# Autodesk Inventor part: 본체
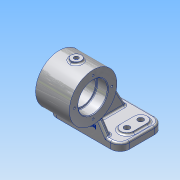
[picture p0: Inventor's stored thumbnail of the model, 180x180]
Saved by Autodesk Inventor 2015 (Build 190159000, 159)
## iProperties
Created: 2023-08
Part Number: 본체
Material: 알루미늄 6061
Document SubType Name: Modeling
Designer: 학생용
Density: 2.7 g/cm^3
Appearance: 알루미늄 - 평지
Mass: 777.808 g
Surface Area: 536.466 cm^2
Volume: 288.077 cm^3
Author: 학생용
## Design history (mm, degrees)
sketch "스케치1"
  geometry: L1 (-58, 12)-(58, 12); L2 (58, 12)-(58, 0); L3 (58, 0)-(-58, 0); L4 (-58, 0)-(-58, 12); 2 further points
  constraints: 8 end point, 2 parallel, 1 coincident, 1 horizontal, 1 midpoint, 1 perpendicular
  dimensions: "d0" = 116 distance of L2.end L3.end; "d1" = 12 distance of L1.end L2.end
extrude "돌출1" new body sketch "스케치1" stored distance "d2" = 70; taper "d3" = 0 deg
fillet "모깎기1" dims "d4" = 15
sketch "스케치2"
  geometry: L1 (84, 28)-(84, 50); L2 (94, 28)-(94, 50); L3 (74, 50)-(74, 28); L4 (43, 35)-(43, 87.935); L5 (2, 28)-(2, 50); L6 (-8, 28)-(-8, 50); L7 (12, 50)-(12, 28); L8 (0, 70)-(86, 70) reference; L9 (101, 15)-(101, 55) reference; A1 r 10 centre (84, 28) between (74, 28) and (94, 28); A2 r 10 centre (84, 50) between (94, 50) and (74, 50); A3 r 10 centre (2, 28) between (-8, 28) and (12, 28); A4 r 10 centre (2, 50) between (12, 50) and (-8, 50); 2 further points
  constraints: 18 end point, 8 point on circle, 6 symmetric about line, 4 centre point, 4 tangent, 2 vertical, 1 midpoint, 1 parallel, 2 other
  dimensions: "d6" = 20 distance between parallel lines of L3 L2; "d26" = 10 distance edge to line of A2 L8; "d28" = 22 distance of L1.start L1.end; "d73" = 82 distance of L1.end L5.end
extrude "돌출2" join sketch "스케치2" distance "d8" = 3; taper "d9" = 0 deg
sketch "스케치3"
  geometry: L1 (94, 28)-(94, 50) reference; L2 (74, 50)-(74, 28) reference; L3 (-8, 50)-(-8, 28) reference; L4 (12, 28)-(12, 50) reference; C1 r 4.5 at (84, 50); C2 r 4.5 at (84, 28); C3 r 4.5 at (2, 50); C4 r 4.5 at (2, 28); A1 r 10 centre (84, 50) between (94, 50) and (74, 50) reference; A2 r 10 centre (84, 28) between (74, 28) and (94, 28) reference; A3 r 10 centre (2, 28) between (-8, 28) and (12, 28) reference; A4 r 10 centre (2, 50) between (12, 50) and (-8, 50) reference; 1 further point
  constraints: 4 centre point, 4 coincident
  dimensions: "d10" = 9 diameter of C1; "d11" = 9 diameter of C2; "d12" = 9 diameter of C3; "d13" = 9 diameter of C4
extrude "돌출3" cut sketch "스케치3" stored distance "d14" = 3; taper "d15" = 0 deg
sketch "스케치4"
  geometry: L1 (12, 7)-(15, 7) reference; C1 r 38 at (70, 47); 1 further point
  constraints: 1 centre point
  dimensions: "d16" = 70 horizontal distance of point (0, 0) C1.centre; "d17" = 40 distance from line of C1.centre L1; "d18" = 76 diameter of C1
extrude "돌출4" join sketch "스케치4" stored distance "d19" = 54; taper "d20" = 0 deg
sketch "스케치5"
  geometry: L1 (-19.159, 37.933)-(-36, 12); L2 (-51, 12)-(-31, 12) reference; L3 (-58, 12)-(-58, 0) reference; L4 (0, 0)-(0, 51.675); L5 (19.159, 37.933)-(36, 12); L6 (-36, 12)-(36, 12); L7 (31, 12)-(51, 12) reference; L8 (-19.159, 37.933)-(19.159, 37.933)
  constraints: 10 end point, 2 symmetric about line, 1 collinear, 1 horizontal, 1 point on line, 1 vertical
  dimensions: "d21" = 33 deg angle of L3 L1; "d22" = 22 distance of L3.start L1.end; "d23" = 38.31786 distance of L1.start L5.start
extrude "돌출5" join sketch "스케치5" distance "d24" = 8; taper "d25" = 0 deg
sketch "스케치6"
  geometry: L1 (12, -27)-(87.882, 13.471); L2 (12, -35)-(0, -35) reference; L3 (12, -20)-(12, -35) reference; 2 further points
  constraints: 2 end point, 1 point on line, 3 other
  dimensions: "d77" = 8 distance from line of L2 L1.start
feature "리브1" sketch "스케치6" dims "d29" = 1, "d30" = 12, "d31" = 0, "d32" = 0, "d33" = 1, "d34" = 1
node "작업 평면2"
  node "작업 평면1"
sketch "스케치7"
  geometry: L1 (27, -38)-(27, 38) reference; L2 (27, 0)-(-27, 0); L3 (27, 0)-(27, 23.5); L4 (27, 23.5)-(10, 23.5); L5 (10, 23.5)-(10, 20.5); L6 (10, 20.5)-(-10, 20.5); L7 (-27, 38)-(-27, -38) reference; L8 (-27, 0)-(-27, 23.5); L9 (-27, 23.5)-(-10, 23.5); L10 (-10, 23.5)-(-10, 20.5); 1 further point
  constraints: 16 end point, 3 horizontal, 3 perpendicular, 2 point on line, 1 midpoint
  dimensions: "d36" = 47 diameter of L4 L2; "d37" = 41 diameter of L6 L2; "d38" = 17 distance of L3.end L4.end; "d40" = 17 distance of L8.end L9.end; "d41" = 47 diameter of L9 L2
revolve "회전1" sketch "스케치7" stored, may be unused: angle "d42" = 90 deg
sketch "스케치8" dims "d43" = 60
  geometry: C1 r 20.5 at (0, 0) reference; 6 further points
  constraints: 2 vertical alignment, 1 coincident, 7 other
  dimensions: "d46" = 360 deg dimension on C1.centre point (0, 30) (derived)
hole "구멍1" sketch "스케치8" at (0, 30), (-30, 0), (0, -30), (30, 0) diameter "d48" = 3.242; stored, may be unused: countersink angle "d52" = 90 deg, drill point angle "d54" = 120 deg; dims "d49" = 8, "d50" = 4, "d51" = 2, "d53" = 10
node "작업 평면3"
sketch "스케치9"
  geometry: L1 (27, 1.621)-(27, -1.621) reference; L2 (27, 0)-(-27, 0); L3 (-27, -1.621)-(-27, 1.621) reference; C1 r 8 at (0, 0); 2 further points
  constraints: 3 midpoint, 2 end point, 1 centre point, 1 coincident, 1 vertical alignment
  dimensions: "d55" = 16 diameter of C1
extrude "돌출6" join sketch "스케치9" distance "d56" = 3; taper "d58" = 0 deg; dims "d57" = 4, "d59" = 0
sketch "스케치10"
  geometry: C1 r 8 at (0, 0) reference; 2 further points
  constraints: 1 coincident
hole "구멍2" sketch "스케치10" at (0, 0) diameter "d60" = 5.188; stored, may be unused: countersink angle "d64" = 90 deg, drill point angle "d66" = 120 deg; dims "d61" = 25, "d62" = 7, "d63" = 4, "d65" = 30
chamfer "모따기1" distance "d67" = 1; stored, may be unused: second distance "d68" = 2, angle "d69" = 45 deg
fillet "모깎기2" dims "d70" = 1
fillet "모깎기3" dims "d71" = 3
fillet "모깎기4" dims "d72" = 3
sketch "스케치11"
  geometry: 2 further points
  constraints: 1 vertical alignment, 1 other
  dimensions: "d74" = 19 distance of point (0, 0) point (0, 19)
feature "엠보싱1" sketch "스케치11" dims "d0" = 116, "d1" = 12, "d6" = 20, "d26" = 10, "d28" = 22, "d73" = 82, "d75" = 0.5, "d76" = 0
node "솔리드1"
mirror "대칭1"
node "투영된 루프1"
node "투영된 루프2"
other parameters: "d35" = -38
